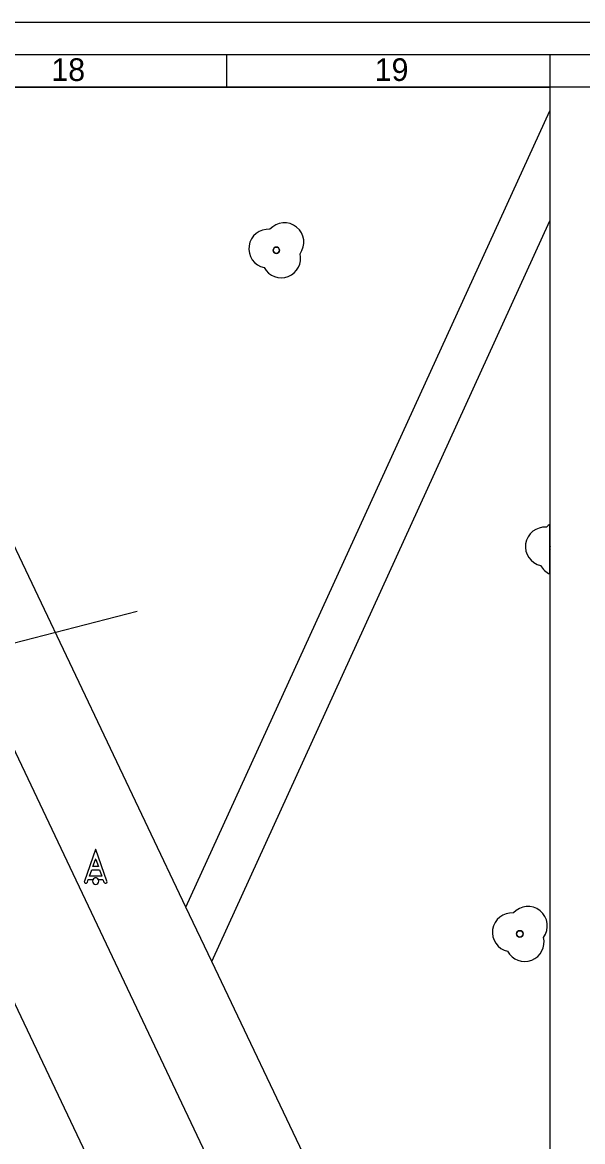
# Model space of a CAD drawing. Extents: x 192672 to 192910, y 446344 to 446512.
# Drawn here: x 192844.33 to 192861.65, y 446477.15 to 446511.76 of the extents above; entities that cross this region are included whole.
import ezdxf

# ---------------------------------------------------------------- set-up
doc = ezdxf.new("R2010")
doc.units = 0
for name, color, linetype in [('( Toegevoegd 29-11-2021 14_41_42) wegdeel vlak', 7, 'Continuous'), ('1010 viewport', 7, 'Continuous'), ('B-OI-RI-RIOOLVRIJVERVAL-G', 7, 'Continuous'), ('boom', 7, 'Continuous'), ('bovenleidingmast', 7, 'Continuous'), ('kant open verharding', 7, 'Continuous'), ('X-XX-AL-TEKENBLAD-S', 7, 'Continuous')]:
    doc.layers.add(name, color=color, linetype=linetype)

msp = doc.modelspace()

# ---------------------------------------------------------------- linework, layer by layer
at = {"layer": '( Toegevoegd 29-11-2021 14_41_42) wegdeel vlak'}
for p, q in [((192849.384, 446484.404), (192860.643, 446509.019)), ((192850.183, 446482.725), (192860.643, 446505.623))]:
    msp.add_line(p, q, dxfattribs=at)
at = {"layer": '1010 viewport'}
msp.add_lwpolyline([(192675.743, 446509.756), (192860.643, 446509.756), (192860.643, 446345.556), (192675.743, 446345.556)], close=True, dxfattribs=at)
at = {"layer": 'B-OI-RI-RIOOLVRIJVERVAL-G'}
for points in [[(192842.435, 446492.149), (192847.881, 446493.556)], [(192838.8, 446492.53), (192848.69, 446471.73)]]:
    msp.add_lwpolyline(points, dxfattribs=at)
at = {"layer": 'boom'}
for p, q in [((192860.643, 446495.55), (192860.643, 446496.247)), ((192860.643, 446495.45), (192860.643, 446495.55)), ((192860.643, 446494.699), (192860.643, 446495.45))]:
    msp.add_line(p, q, dxfattribs=at)
for centre in [(192852.18, 446504.71), (192859.71, 446483.574)]:
    msp.add_circle(centre, 0.1, dxfattribs=at)
for centre, radius, start, end in [((192852.43, 446504.96), 0.6, 323.5446, 138.4658), ((192851.93, 446504.76), 0.6, 85.137, 257.7544), ((192852.18, 446504.71), 0.1, 0, 180), ((192852.18, 446504.71), 0.1, 180, 0), ((192852.33, 446504.46), 0.6, 208.5058, 13.8356), ((192860.48, 446495.55), 0.6, 85.137, 257.7544), ((192860.98, 446495.75), 0.6, 124.1275, 138.4658), ((192860.73, 446495.5), 0.1, 150.0218, 209.9782), ((192860.73, 446495.5), 0.1, 150.0218, 209.9782), ((192860.88, 446495.25), 0.6, 208.5058, 246.7734), ((192859.96, 446483.824), 0.6, 323.5446, 138.4658), ((192859.46, 446483.624), 0.6, 85.137, 257.7544), ((192859.71, 446483.574), 0.1, 0, 180), ((192859.86, 446483.324), 0.6, 208.5058, 13.8356), ((192859.71, 446483.574), 0.1, 180, 0)]:
    msp.add_arc(centre, radius, start, end, dxfattribs=at)
at = {"layer": 'bovenleidingmast'}
for p, q in [((192846.583, 446486.18), (192846.242, 446485.207)), ((192846.942, 446485.207), (192846.601, 446486.18))]:
    msp.add_line(p, q, dxfattribs=at)
for points in [[(192846.601, 446485.877), (192846.679, 446485.657), (192846.505, 446485.657), (192846.583, 446485.877)], [(192846.336, 446485.174), (192846.365, 446485.257), (192846.505, 446485.257)], [(192846.679, 446485.257), (192846.819, 446485.257), (192846.848, 446485.174)]]:
    msp.add_lwpolyline(points, dxfattribs=at)
msp.add_lwpolyline([(192846.714, 446485.557), (192846.784, 446485.357), (192846.4, 446485.357), (192846.47, 446485.557)], close=True, dxfattribs=at)
for centre, radius, start, end in [((192846.592, 446486.177), 0.01, 19.29, 160.71), ((192846.592, 446485.874), 0.01, 19.29, 160.71), ((192846.289, 446485.19), 0.05, 160.71, 340.71), ((192846.592, 446485.207), 0.1, 0, 180), ((192846.592, 446485.207), 0.1, 180, 0), ((192846.592, 446485.207), 0.1, 30, 150), ((192846.895, 446485.19), 0.05, 199.29, 19.29)]:
    msp.add_arc(centre, radius, start, end, dxfattribs=at)
at = {"layer": 'kant open verharding'}
for p, q in [((192849.384, 446484.404), (192837.327, 446509.756)), ((192835.606, 446507.086), (192852.92, 446470.626)), ((192850.183, 446482.725), (192849.384, 446484.404)), ((192855.223, 446472.129), (192850.183, 446482.725))]:
    msp.add_line(p, q, dxfattribs=at)
at = {"layer": 'X-XX-AL-TEKENBLAD-S'}
for p, q in [((192909.543, 446511.756), (192671.743, 446511.756)), ((192908.543, 446510.756), (192674.743, 446510.756)), ((192850.643, 446510.756), (192850.643, 446509.756)), ((192860.643, 446510.756), (192860.643, 446509.756))]:
    msp.add_line(p, q, dxfattribs=at)
msp.add_lwpolyline([(192675.743, 446345.556), (192907.543, 446345.556), (192907.543, 446509.756), (192675.743, 446509.756)], close=True, dxfattribs=at)

# ---------------------------------------------------------------- texts
for s, p in [('18', (192845.224, 446509.945)), ('19', (192855.224, 446509.945))]:
    msp.add_text(s, height=0.7, dxfattribs=at).set_placement(p)

doc.saveas('drawing.dxf')
